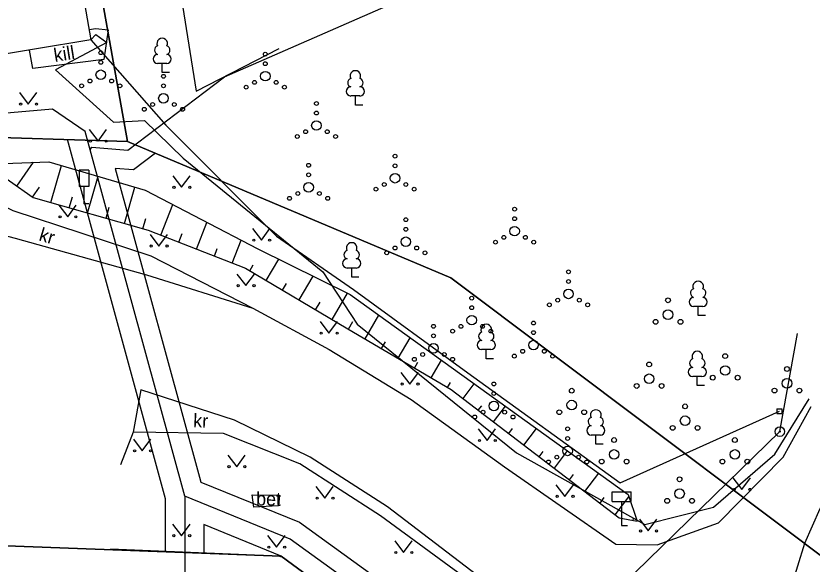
# Model space of a CAD drawing. Extents: x 554947 to 555436, y 6564938 to 6565792.
# Drawn here: x 555228.52 to 555270.11, y 6565583.53 to 6565612.16 of the extents above; entities that cross this region are included whole.
import ezdxf

# ---------------------------------------------------------------- set-up
doc = ezdxf.new("R2010")
doc.units = 0
for name, color, linetype in [('AED', 7, 'Continuous'), ('HALJASTUS', 7, 'Continuous'), ('HOONE', 7, 'Continuous'), ('KASUTUSALA', 7, 'Continuous'), ('LIIKLUS', 7, 'Continuous'), ('MPKAABEL', 7, 'Continuous'), ('MPOHULIIN', 7, 'Continuous'), ('PIIR', 7, 'Continuous'), ('POST', 7, 'Continuous'), ('PR_SIDE', 7, 'Continuous'), ('PUU', 7, 'Continuous'), ('RELJEEF', 7, 'Continuous'), ('TEE', 7, 'Continuous')]:
    doc.layers.add(name, color=color, linetype=linetype)

msp = doc.modelspace()

# ---------------------------------------------------------------- linework, layer by layer
at = {"layer": 'AED'}
for p, q in [((555268.277, 6565591.648), (555268.277, 6565591.398)), ((555268.277, 6565591.648), (555268.527, 6565591.648)), ((555268.527, 6565591.648), (555268.527, 6565591.398)), ((555268.277, 6565591.398), (555268.527, 6565591.398))]:
    msp.add_line(p, q, dxfattribs=at)
for points in [[(555232.436, 6565610.906), (555236.358, 6565606.45), (555242.129, 6565600.656), (555246.155, 6565597.882), (555252.128, 6565593.519), (555260.095, 6565587.775), (555268.402, 6565591.523)], [(555257.388, 6565572.989), (555251.782, 6565577.142), (555242.434, 6565583.901), (555242.233, 6565583.941), (555233.453, 6565584.321)]]:
    msp.add_lwpolyline(points, dxfattribs=at)
at = {"layer": 'HALJASTUS'}
for p, q in [((555228.702, 6565608.164), (555229.166, 6565607.558)), ((555229.166, 6565607.558), (555229.611, 6565608.164)), ((555232.345, 6565606.223), (555232.808, 6565605.616)), ((555232.808, 6565605.616), (555233.254, 6565606.223)), ((555236.713, 6565603.817), (555237.176, 6565603.21)), ((555237.176, 6565603.21), (555237.622, 6565603.817)), ((555230.761, 6565602.272), (555231.225, 6565601.665)), ((555231.225, 6565601.665), (555231.67, 6565602.272)), ((555240.883, 6565601.058), (555241.346, 6565600.451)), ((555241.346, 6565600.451), (555241.792, 6565601.058)), ((555235.524, 6565600.751), (555235.988, 6565600.144)), ((555235.988, 6565600.144), (555236.433, 6565600.751)), ((555240.066, 6565598.683), (555240.53, 6565598.076)), ((555240.53, 6565598.076), (555240.975, 6565598.683)), ((555244.406, 6565596.2), (555244.87, 6565595.593)), ((555244.87, 6565595.593), (555245.315, 6565596.2)), ((555248.633, 6565593.543), (555249.097, 6565592.937)), ((555249.097, 6565592.937), (555249.542, 6565593.543)), ((555252.67, 6565590.593), (555253.134, 6565589.986)), ((555253.134, 6565589.986), (555253.579, 6565590.593)), ((555234.659, 6565590.056), (555235.122, 6565589.45)), ((555235.122, 6565589.45), (555235.568, 6565590.056)), ((555239.59, 6565589.226), (555240.053, 6565588.62)), ((555240.053, 6565588.62), (555240.499, 6565589.226)), ((555265.979, 6565588.04), (555266.442, 6565587.434)), ((555266.442, 6565587.434), (555266.888, 6565588.04)), ((555244.191, 6565587.586), (555244.655, 6565586.979)), ((555244.655, 6565586.979), (555245.1, 6565587.586)), ((555256.732, 6565587.677), (555257.195, 6565587.07)), ((555257.195, 6565587.07), (555257.641, 6565587.677)), ((555236.705, 6565585.623), (555237.169, 6565585.017)), ((555237.169, 6565585.017), (555237.614, 6565585.623)), ((555261.092, 6565585.871), (555261.555, 6565585.264)), ((555261.555, 6565585.264), (555262.001, 6565585.871)), ((555241.67, 6565585.027), (555242.133, 6565584.421)), ((555242.133, 6565584.421), (555242.579, 6565585.027)), ((555248.307, 6565584.746), (555248.77, 6565584.139)), ((555248.77, 6565584.139), (555249.216, 6565584.746))]:
    msp.add_line(p, q, dxfattribs=at)
for points in [[(555237.448, 6565630.434), (555234.711, 6565628.766), (555234.594, 6565621.78), (555237.038, 6565613.917), (555237.935, 6565608.224), (555242.277, 6565610.46)], [(555232.436, 6565610.906), (555232.688, 6565611.189), (555233.276, 6565610.777), (555230.59, 6565609.352), (555233.609, 6565606.609), (555235.228, 6565606.695), (555237.256, 6565604.74), (555244.547, 6565598.797), (555246.343, 6565596.071), (555254.665, 6565589.351), (555261.368, 6565585.597), (555264.956, 6565586.512), (555268.159, 6565589.281), (555269.967, 6565592.17)]]:
    msp.add_lwpolyline(points, dxfattribs=at)
for centre, radius in [((555232.951, 6565610.238), 0.1), ((555241.546, 6565610.166), 0.1), ((555232.951, 6565609.738), 0.1), ((555241.546, 6565609.666), 0.1), ((555232.951, 6565609.088), 0.25), ((555236.225, 6565609.009), 0.1), ((555241.546, 6565609.016), 0.25), ((555231.951, 6565608.513), 0.1), ((555232.386, 6565608.763), 0.1), ((555233.516, 6565608.763), 0.1), ((555233.951, 6565608.513), 0.1), ((555236.225, 6565608.509), 0.1), ((555240.546, 6565608.441), 0.1), ((555240.981, 6565608.691), 0.1), ((555242.111, 6565608.691), 0.1), ((555242.546, 6565608.441), 0.1), ((555236.225, 6565607.859), 0.25), ((555244.218, 6565607.588), 0.1), ((555228.765, 6565607.558), 0.055), ((555229.593, 6565607.558), 0.055), ((555235.225, 6565607.284), 0.1), ((555235.66, 6565607.534), 0.1), ((555236.79, 6565607.534), 0.1), ((555237.225, 6565607.284), 0.1), ((555244.218, 6565607.088), 0.1), ((555244.218, 6565606.438), 0.25), ((555243.653, 6565606.113), 0.1), ((555244.783, 6565606.113), 0.1), ((555232.407, 6565605.616), 0.055), ((555233.236, 6565605.616), 0.055), ((555243.218, 6565605.863), 0.1), ((555245.218, 6565605.863), 0.1), ((555248.326, 6565604.835), 0.1), ((555243.809, 6565604.36), 0.1), ((555248.326, 6565604.335), 0.1), ((555243.809, 6565603.86), 0.1), ((555248.326, 6565603.685), 0.25), ((555236.775, 6565603.21), 0.055), ((555237.604, 6565603.21), 0.055), ((555243.809, 6565603.21), 0.25), ((555247.326, 6565603.11), 0.1), ((555247.761, 6565603.36), 0.1), ((555248.891, 6565603.36), 0.1), ((555249.326, 6565603.11), 0.1), ((555242.809, 6565602.635), 0.1), ((555243.244, 6565602.885), 0.1), ((555244.374, 6565602.885), 0.1), ((555244.809, 6565602.635), 0.1), ((555254.571, 6565602.071), 0.1), ((555230.824, 6565601.665), 0.055), ((555231.652, 6565601.665), 0.055), ((555248.889, 6565601.517), 0.1), ((555254.571, 6565601.571), 0.1), ((555248.889, 6565601.017), 0.1), ((555254.571, 6565600.921), 0.25), ((555248.889, 6565600.367), 0.25), ((555254.006, 6565600.596), 0.1), ((555255.136, 6565600.596), 0.1), ((555235.587, 6565600.144), 0.055), ((555236.415, 6565600.144), 0.055), ((555240.945, 6565600.451), 0.055), ((555241.774, 6565600.451), 0.055), ((555253.571, 6565600.346), 0.1), ((555255.571, 6565600.346), 0.1), ((555247.889, 6565599.792), 0.1), ((555248.324, 6565600.042), 0.1), ((555249.454, 6565600.042), 0.1), ((555249.889, 6565599.792), 0.1), ((555257.388, 6565598.795), 0.1), ((555240.129, 6565598.076), 0.055), ((555240.957, 6565598.076), 0.055), ((555257.388, 6565598.295), 0.1), ((555257.388, 6565597.645), 0.25), ((555252.332, 6565597.421), 0.1), ((555256.823, 6565597.32), 0.1), ((555257.953, 6565597.32), 0.1), ((555252.332, 6565596.921), 0.1), ((555256.388, 6565597.07), 0.1), ((555258.388, 6565597.07), 0.1), ((555252.332, 6565596.271), 0.25), ((555250.334, 6565595.952), 0.1), ((555251.767, 6565595.946), 0.1), ((555252.897, 6565595.946), 0.1), ((555255.558, 6565596.121), 0.1), ((555244.469, 6565595.593), 0.055), ((555245.297, 6565595.593), 0.055), ((555251.332, 6565595.696), 0.1), ((555253.332, 6565595.696), 0.1), ((555255.558, 6565595.621), 0.1), ((555250.334, 6565595.452), 0.1), ((555255.558, 6565594.971), 0.25), ((555250.334, 6565594.802), 0.25), ((555249.769, 6565594.477), 0.1), ((555250.899, 6565594.477), 0.1), ((555254.558, 6565594.396), 0.1), ((555254.993, 6565594.646), 0.1), ((555256.123, 6565594.646), 0.1), ((555256.558, 6565594.396), 0.1), ((555249.334, 6565594.227), 0.1), ((555251.334, 6565594.227), 0.1), ((555248.696, 6565592.937), 0.055), ((555249.525, 6565592.937), 0.055), ((555253.488, 6565592.94), 0.1), ((555253.488, 6565592.44), 0.1), ((555253.488, 6565591.79), 0.25), ((555252.923, 6565591.465), 0.1), ((555254.053, 6565591.465), 0.1), ((555252.488, 6565591.215), 0.1), ((555254.488, 6565591.215), 0.1), ((555257.341, 6565590.594), 0.1), ((555257.341, 6565590.094), 0.1), ((555252.733, 6565589.986), 0.055), ((555253.561, 6565589.986), 0.055), ((555234.721, 6565589.45), 0.055), ((555235.55, 6565589.45), 0.055), ((555257.341, 6565589.444), 0.25), ((555256.341, 6565588.869), 0.1), ((555256.776, 6565589.119), 0.1), ((555257.906, 6565589.119), 0.1), ((555258.341, 6565588.869), 0.1), ((555239.652, 6565588.62), 0.055), ((555240.481, 6565588.62), 0.055), ((555266.041, 6565587.434), 0.055), ((555266.87, 6565587.434), 0.055), ((555244.254, 6565586.979), 0.055), ((555245.082, 6565586.979), 0.055), ((555256.794, 6565587.07), 0.055), ((555257.623, 6565587.07), 0.055), ((555261.154, 6565585.264), 0.055), ((555261.983, 6565585.264), 0.055), ((555236.768, 6565585.017), 0.055), ((555237.597, 6565585.017), 0.055), ((555241.732, 6565584.421), 0.055), ((555242.561, 6565584.421), 0.055), ((555248.369, 6565584.139), 0.055), ((555249.198, 6565584.139), 0.055)]:
    msp.add_circle(centre, radius, dxfattribs=at)
at = {"layer": 'HOONE'}
msp.add_lwpolyline([(555227.207, 6565620.08), (555230.727, 6565620.695), (555232.436, 6565610.906), (555223.594, 6565609.458), (555222.944, 6565613.428)], dxfattribs=at)
at = {"layer": 'KASUTUSALA'}
msp.add_lwpolyline([(555330.79, 6565520.761), (555305.197, 6565537.964), (555302.6, 6565539.71), (555242.37, 6565583.94), (555238.34, 6565585.593), (555238.34, 6565584.092), (555236.34, 6565584.168), (555236.34, 6565586.946), (555231.217, 6565605.702), (555233.309, 6565605.634), (555234.35, 6565605.6), (555235.803, 6565604.987), (555234.66, 6565604.12), (555233.701, 6565604.199), (555238.103, 6565588.08), (555238.175, 6565587.82), (555243.331, 6565585.721), (555250.029, 6565580.878), (555260.82, 6565573.213), (555265.213, 6565569.964), (555284.475, 6565555.644), (555289.407, 6565551.783), (555304.515, 6565541.003), (555310.277, 6565536.492)], dxfattribs=at)
at = {"layer": 'LIIKLUS'}
for p, q in [((555231.823, 6565604.106), (555231.823, 6565603.256)), ((555232.323, 6565604.106), (555231.823, 6565604.106)), ((555232.323, 6565604.106), (555232.323, 6565603.256)), ((555232.323, 6565603.256), (555231.823, 6565603.256)), ((555232.073, 6565603.256), (555232.073, 6565602.356)), ((555232.323, 6565602.356), (555232.073, 6565602.356)), ((555259.661, 6565587.299), (555260.661, 6565587.299)), ((555259.661, 6565586.799), (555259.661, 6565587.299)), ((555260.661, 6565586.799), (555260.661, 6565587.299)), ((555259.661, 6565586.799), (555260.661, 6565586.799)), ((555260.161, 6565586.799), (555260.161, 6565585.549)), ((555260.161, 6565585.549), (555260.461, 6565585.549))]:
    msp.add_line(p, q, dxfattribs=at)
at = {"layer": 'MPKAABEL'}
msp.add_lwpolyline([(555232.436, 6565610.906), (555236.358, 6565606.45), (555242.129, 6565600.656), (555246.155, 6565597.882), (555252.128, 6565593.519), (555260.095, 6565587.775), (555268.402, 6565591.523)], dxfattribs=at)
at = {"layer": 'MPOHULIIN'}
for points in [[(555268.428, 6565590.453), (555269.348, 6565595.57)], [(555252.652, 6565575.082), (555268.428, 6565590.453)]]:
    msp.add_lwpolyline(points, dxfattribs=at)
at = {"layer": 'PIIR'}
for points in [[(555193.24, 6565604.68), (555183.94, 6565663.24), (555223.17, 6565668.21), (555234.35, 6565605.6), (555225.47, 6565605.89), (555193.7, 6565602.7)], [(555121.18, 6565602.26), (555138.98, 6565580.6), (555179.42, 6565586.32), (555242.37, 6565583.94), (555302.6, 6565539.71), (555287.77, 6565518.56), (555207.29, 6565506.14), (555200.64, 6565496.23), (555185.97, 6565502.75), (555177.68, 6565506.44), (555171.49, 6565510.85), (555162.05, 6565514.45), (555140.65, 6565513.25), (555139.49, 6565523.98), (555139.26, 6565529.51), (555141.68, 6565537.52), (555139.64, 6565543.1), (555131.01, 6565550.06), (555126.35, 6565558.74), (555119.63, 6565564.84), (555105.26, 6565587.71), (555099.5, 6565594.91), (555116.17, 6565610.5)]]:
    msp.add_lwpolyline(points, close=True, dxfattribs=at)
for points in [[(555374.15, 6565660.24), (555410.9, 6565638.65), (555418.94, 6565635.85), (555435.71, 6565632.72), (555428.83, 6565620.98), (555419.65, 6565609.54), (555361.56, 6565549.57), (555350.68, 6565540.44), (555343.81, 6565536.56), (555330.71, 6565538.85), (555251.24, 6565598.48), (555234.35, 6565605.6), (555223.17, 6565668.21)], [(555144.16, 6565410.6), (555124.27, 6565454.45), (555113.82, 6565475.68), (555076.76, 6565542.38), (555065.78, 6565566.7), (555060.42, 6565583.26), (555057.22, 6565600.73), (555056.61, 6565622.91), (555063.43, 6565647.29), (555114.24, 6565634), (555129.77, 6565611.2), (555130.73, 6565621.32), (555138.66, 6565615.26), (555160.12, 6565598.86), (555193.24, 6565604.68), (555193.7, 6565602.7), (555225.47, 6565605.89), (555234.35, 6565605.6), (555251.24, 6565598.48), (555330.71, 6565538.85), (555343.81, 6565536.56), (555350.68, 6565540.44), (555361.56, 6565549.57), (555393.069, 6565582.099)], [(555393.069, 6565560.972), (555353.12, 6565523.87), (555343.14, 6565512.46), (555302.6, 6565539.71), (555242.37, 6565583.94), (555179.42, 6565586.32), (555138.98, 6565580.6), (555121.18, 6565602.26), (555116.17, 6565610.5), (555109.96, 6565624.83), (555093.56, 6565628.47), (555079.04, 6565618.4), (555074.13, 6565607.82), (555075.34, 6565593.24), (555091.74, 6565551.94), (555171.91, 6565394.64), (555191.35, 6565341.19), (555195.08, 6565294.61), (555195.28, 6565271.63), (555191.64, 6565237.48)]]:
    msp.add_lwpolyline(points, dxfattribs=at)
at = {"layer": 'POST'}
for radius in [0.25, 0.0234]:
    msp.add_circle((555268.428, 6565590.453), radius, dxfattribs=at)
at = {"layer": 'PR_SIDE'}
for points in [[(555232.399, 6565605.169), (555232.478, 6565605.304), (555234.361, 6565605.148), (555239.41, 6565608.98), (555257.145, 6565616.752), (555281.799, 6565659.829), (555291.678, 6565666.126), (555336.528, 6565656.68), (555340.549, 6565660.528)], [(555232.137, 6565606.132), (555230.425, 6565607.283), (555207.996, 6565605.334), (555203.457, 6565604.767), (555201.376, 6565605.797)], [(555309.355, 6565535.944), (555304.351, 6565539.861), (555303.916, 6565540.202), (555288.808, 6565550.982), (555283.868, 6565554.848), (555264.618, 6565569.161), (555260.234, 6565572.403), (555249.446, 6565580.065), (555242.843, 6565584.84), (555237.34, 6565587.08), (555232.399, 6565605.169), (555232.137, 6565606.132)], [(555237.34, 6565587.08), (555237.34, 6565565.16), (555226.585, 6565555.364), (555203.636, 6565543.731), (555203.636, 6565538.53), (555204.984, 6565533.828), (555204.645, 6565532.63)]]:
    msp.add_lwpolyline(points, dxfattribs=at)
at = {"layer": 'PUU'}
for p, q in [((555236.401, 6565609.678), (555235.921, 6565609.678)), ((555236.161, 6565609.203), (555236.161, 6565609.678)), ((555236.541, 6565609.203), (555236.161, 6565609.203)), ((555246.494, 6565607.979), (555246.014, 6565607.979)), ((555246.254, 6565607.504), (555246.254, 6565607.979)), ((555246.634, 6565607.504), (555246.254, 6565607.504)), ((555246.301, 6565598.996), (555245.821, 6565598.996)), ((555246.061, 6565598.521), (555246.061, 6565598.996)), ((555246.441, 6565598.521), (555246.061, 6565598.521)), ((555264.402, 6565596.984), (555263.922, 6565596.984)), ((555264.162, 6565596.509), (555264.162, 6565596.984)), ((555264.542, 6565596.509), (555264.162, 6565596.509)), ((555253.33, 6565594.735), (555252.85, 6565594.735)), ((555253.09, 6565594.26), (555253.09, 6565594.735)), ((555253.47, 6565594.26), (555253.09, 6565594.26)), ((555264.357, 6565593.327), (555263.877, 6565593.327)), ((555264.117, 6565592.852), (555264.117, 6565593.327)), ((555264.497, 6565592.852), (555264.117, 6565592.852)), ((555259.054, 6565590.273), (555258.574, 6565590.273)), ((555258.814, 6565589.798), (555258.814, 6565590.273)), ((555259.194, 6565589.798), (555258.814, 6565589.798))]:
    msp.add_line(p, q, dxfattribs=at)
for centre, radius in [((555262.588, 6565597.311), 0.125), ((555262.588, 6565596.561), 0.25), ((555261.938, 6565596.186), 0.125), ((555263.238, 6565596.186), 0.125), ((555265.574, 6565594.395), 0.125), ((555261.601, 6565593.962), 0.125), ((555265.574, 6565593.645), 0.25), ((555268.8, 6565593.721), 0.125), ((555261.601, 6565593.212), 0.25), ((555264.924, 6565593.27), 0.125), ((555266.224, 6565593.27), 0.125), ((555268.8, 6565592.971), 0.25), ((555257.556, 6565592.589), 0.125), ((555260.951, 6565592.837), 0.125), ((555262.251, 6565592.837), 0.125), ((555268.15, 6565592.596), 0.125), ((555269.45, 6565592.596), 0.125), ((555257.556, 6565591.839), 0.25), ((555263.479, 6565591.77), 0.125), ((555256.906, 6565591.464), 0.125), ((555258.206, 6565591.464), 0.125), ((555263.479, 6565591.02), 0.25), ((555262.829, 6565590.645), 0.125), ((555264.129, 6565590.645), 0.125), ((555259.771, 6565590.011), 0.125), ((555266.079, 6565590.011), 0.125), ((555259.771, 6565589.261), 0.25), ((555266.079, 6565589.261), 0.25), ((555259.121, 6565588.886), 0.125), ((555260.421, 6565588.886), 0.125), ((555265.429, 6565588.886), 0.125), ((555266.729, 6565588.886), 0.125), ((555263.19, 6565587.963), 0.125), ((555263.19, 6565587.213), 0.25), ((555262.54, 6565586.838), 0.125), ((555263.84, 6565586.838), 0.125)]:
    msp.add_circle(centre, radius, dxfattribs=at)
for centre, radius, start, end in [((555236.161, 6565610.723), 0.277, 332.5799, 207.4201), ((555235.991, 6565610.375), 0.233, 109.0217, 253.1415), ((555236.331, 6565610.375), 0.233, 286.8508, 70.9859), ((555235.924, 6565609.915), 0.238, 90.0016, 269.3953), ((555236.398, 6565609.915), 0.238, 270.6047, 89.9984), ((555246.254, 6565609.024), 0.277, 332.5799, 207.4201), ((555246.084, 6565608.676), 0.233, 109.0217, 253.1415), ((555246.424, 6565608.676), 0.233, 286.8508, 70.9859), ((555246.016, 6565608.216), 0.238, 90.0016, 269.3953), ((555246.491, 6565608.216), 0.238, 270.6047, 89.9984), ((555246.061, 6565600.041), 0.277, 332.5799, 207.4201), ((555245.891, 6565599.694), 0.233, 109.0217, 253.1415), ((555246.231, 6565599.694), 0.233, 286.8508, 70.9859), ((555245.824, 6565599.234), 0.238, 90.0016, 269.3953), ((555246.299, 6565599.234), 0.238, 270.6047, 89.9984), ((555264.162, 6565598.029), 0.277, 332.5799, 207.4201), ((555263.992, 6565597.681), 0.233, 109.0217, 253.1415), ((555264.332, 6565597.681), 0.233, 286.8508, 70.9859), ((555263.925, 6565597.221), 0.238, 90.0016, 269.3953), ((555264.399, 6565597.221), 0.238, 270.6047, 89.9984), ((555253.09, 6565595.781), 0.277, 332.5799, 207.4201), ((555252.92, 6565595.433), 0.233, 109.0217, 253.1415), ((555253.26, 6565595.433), 0.233, 286.8508, 70.9859), ((555252.853, 6565594.973), 0.238, 90.0016, 269.3953), ((555253.328, 6565594.973), 0.238, 270.6047, 89.9984), ((555264.117, 6565594.372), 0.277, 332.5799, 207.4201), ((555263.947, 6565594.024), 0.233, 109.0217, 253.1415), ((555264.287, 6565594.024), 0.233, 286.8508, 70.9859), ((555263.88, 6565593.564), 0.238, 90.0016, 269.3953), ((555264.355, 6565593.564), 0.238, 270.6047, 89.9984), ((555258.814, 6565591.318), 0.277, 332.5799, 207.4201), ((555258.644, 6565590.971), 0.233, 109.0217, 253.1415), ((555258.984, 6565590.971), 0.233, 286.8508, 70.9859), ((555258.576, 6565590.51), 0.238, 90.0016, 269.3953), ((555259.051, 6565590.51), 0.238, 270.6047, 89.9984)]:
    msp.add_arc(centre, radius, start, end, dxfattribs=at)
at = {"layer": 'RELJEEF'}
for p, q in [((555228.564, 6565603.267), (555229.436, 6565604.515)), ((555230.341, 6565602.411), (555230.892, 6565604.355)), ((555232.266, 6565601.867), (555232.809, 6565603.787)), ((555229.384, 6565602.695), (555229.75, 6565603.218)), ((555234.19, 6565601.322), (555234.727, 6565603.219)), ((555231.303, 6565602.139), (555231.468, 6565602.719)), ((555236.092, 6565600.712), (555236.716, 6565602.307)), ((555233.228, 6565601.594), (555233.39, 6565602.167)), ((555235.152, 6565601.049), (555235.305, 6565601.59)), ((555237.955, 6565599.984), (555238.501, 6565601.381)), ((555237.024, 6565600.348), (555237.199, 6565600.797)), ((555239.818, 6565599.256), (555240.286, 6565600.454)), ((555238.887, 6565599.62), (555239.039, 6565600.009)), ((555241.592, 6565598.346), (555242.251, 6565599.46)), ((555240.732, 6565598.855), (555240.918, 6565599.17)), ((555243.314, 6565597.328), (555244.047, 6565598.568)), ((555242.453, 6565597.837), (555242.662, 6565598.19)), ((555245.035, 6565596.31), (555245.843, 6565597.676)), ((555244.175, 6565596.819), (555244.406, 6565597.21)), ((555246.758, 6565595.294), (555247.484, 6565596.527)), ((555245.896, 6565595.801), (555246.128, 6565596.195)), ((555248.482, 6565594.28), (555249.114, 6565595.354)), ((555247.62, 6565594.787), (555247.824, 6565595.133)), ((555249.344, 6565593.773), (555249.519, 6565594.071)), ((555250.206, 6565593.266), (555250.744, 6565594.182)), ((555251.067, 6565592.758), (555251.215, 6565593.009)), ((555251.877, 6565592.174), (555252.465, 6565592.945)), ((555252.672, 6565591.567), (555252.854, 6565591.805)), ((555253.467, 6565590.961), (555254.091, 6565591.778)), ((555254.262, 6565590.354), (555254.455, 6565590.606)), ((555255.057, 6565589.748), (555255.716, 6565590.611)), ((555255.853, 6565589.141), (555256.055, 6565589.407)), ((555256.648, 6565588.535), (555257.341, 6565589.444)), ((555257.443, 6565587.928), (555257.656, 6565588.208)), ((555258.238, 6565587.322), (555258.966, 6565588.277)), ((555259.033, 6565586.715), (555259.257, 6565587.009)), ((555259.828, 6565586.109), (555260.546, 6565587.049)), ((555260.761, 6565585.812), (555260.782, 6565585.923))]:
    msp.add_line(p, q, dxfattribs=at)
for points in [[(555226.924, 6565604.412), (555230.239, 6565604.548), (555235.266, 6565603.059), (555241.163, 6565600), (555245.981, 6565597.608), (555251.809, 6565593.416), (555260.505, 6565587.172), (555260.967, 6565585.773)], [(555226.924, 6565604.412), (555229.414, 6565602.674), (555235.432, 6565600.97), (555240.514, 6565598.984), (555245.865, 6565595.82), (555251.258, 6565592.646), (555260.036, 6565585.95), (555260.967, 6565585.773)]]:
    msp.add_lwpolyline(points, dxfattribs=at)
at = {"layer": 'TEE'}
for points in [[(555232.343, 6565611.444), (555232.688, 6565611.504), (555233.346, 6565611.432), (555233.113, 6565609.886)], [(555233.113, 6565609.886), (555229.405, 6565609.408), (555229.229, 6565610.381)], [(555222.826, 6565609.775), (555223.534, 6565606.972), (555224.328, 6565605.219), (555225.968, 6565603.202), (555228.36, 6565602.005), (555235.567, 6565599.627), (555240.887, 6565596.891)], [(555188.66, 6565597.281), (555201.537, 6565599.665), (555208.847, 6565600.64), (555216.336, 6565601.179), (555217.666, 6565602.458), (555221.722, 6565602.33), (555228.473, 6565600.549), (555235.333, 6565598.633), (555240.887, 6565596.891), (555244.887, 6565594.749), (555249.174, 6565592.129), (555254.043, 6565588.613), (555259.862, 6565584.582), (555262.011, 6565584.54), (555265.231, 6565585.691), (555268.603, 6565589.126), (555270.071, 6565591.77)], [(555309.906, 6565538.03), (555305.168, 6565541.808), (555305.066, 6565542.334), (555294.766, 6565550.531), (555276.823, 6565564.276), (555265.732, 6565572.927), (555259.684, 6565577.587), (555254.787, 6565581.289), (555247.931, 6565586.532), (555243.893, 6565589.125), (555239.934, 6565591.048), (555235.042, 6565592.642), (555234.652, 6565590.428), (555233.978, 6565588.723)], [(555254.087, 6565579.537), (555253.958, 6565580.81), (555252.655, 6565582.326), (555247.572, 6565586.061), (555243.345, 6565588.774), (555239.362, 6565590.351), (555234.652, 6565590.428)], [(555272.683, 6565590.134), (555271.484, 6565588.076), (555270.516, 6565586.416), (555269.723, 6565584.609), (555268.981, 6565582.24), (555268.55, 6565578.954), (555269.504, 6565576.952), (555281.044, 6565568.103), (555297.768, 6565555.508), (555316.66, 6565541.129), (555323.074, 6565536.252), (555328.036, 6565533.009), (555332.837, 6565530.879), (555337.611, 6565529.695), (555343.363, 6565529.946), (555348.456, 6565531.532), (555353.801, 6565534.677), (555358.561, 6565538.499)], [(555240.854, 6565587.15), (555242.289, 6565587.129), (555242.241, 6565586.577), (555240.956, 6565586.51), (555240.854, 6565587.15)]]:
    msp.add_lwpolyline(points, dxfattribs=at)

# ---------------------------------------------------------------- texts
for s, rotation, p in [('kill', 9.0562, (555230.552, 6565609.756)), ('kr', 343.3686, (555229.676, 6565600.446)), ('kr', 357.4887, (555237.769, 6565590.687)), ('bet', 359.1358, (555241.063, 6565586.6))]:
    msp.add_text(s, height=0.7, rotation=rotation, dxfattribs=at).set_placement(p)

doc.saveas('drawing.dxf')
